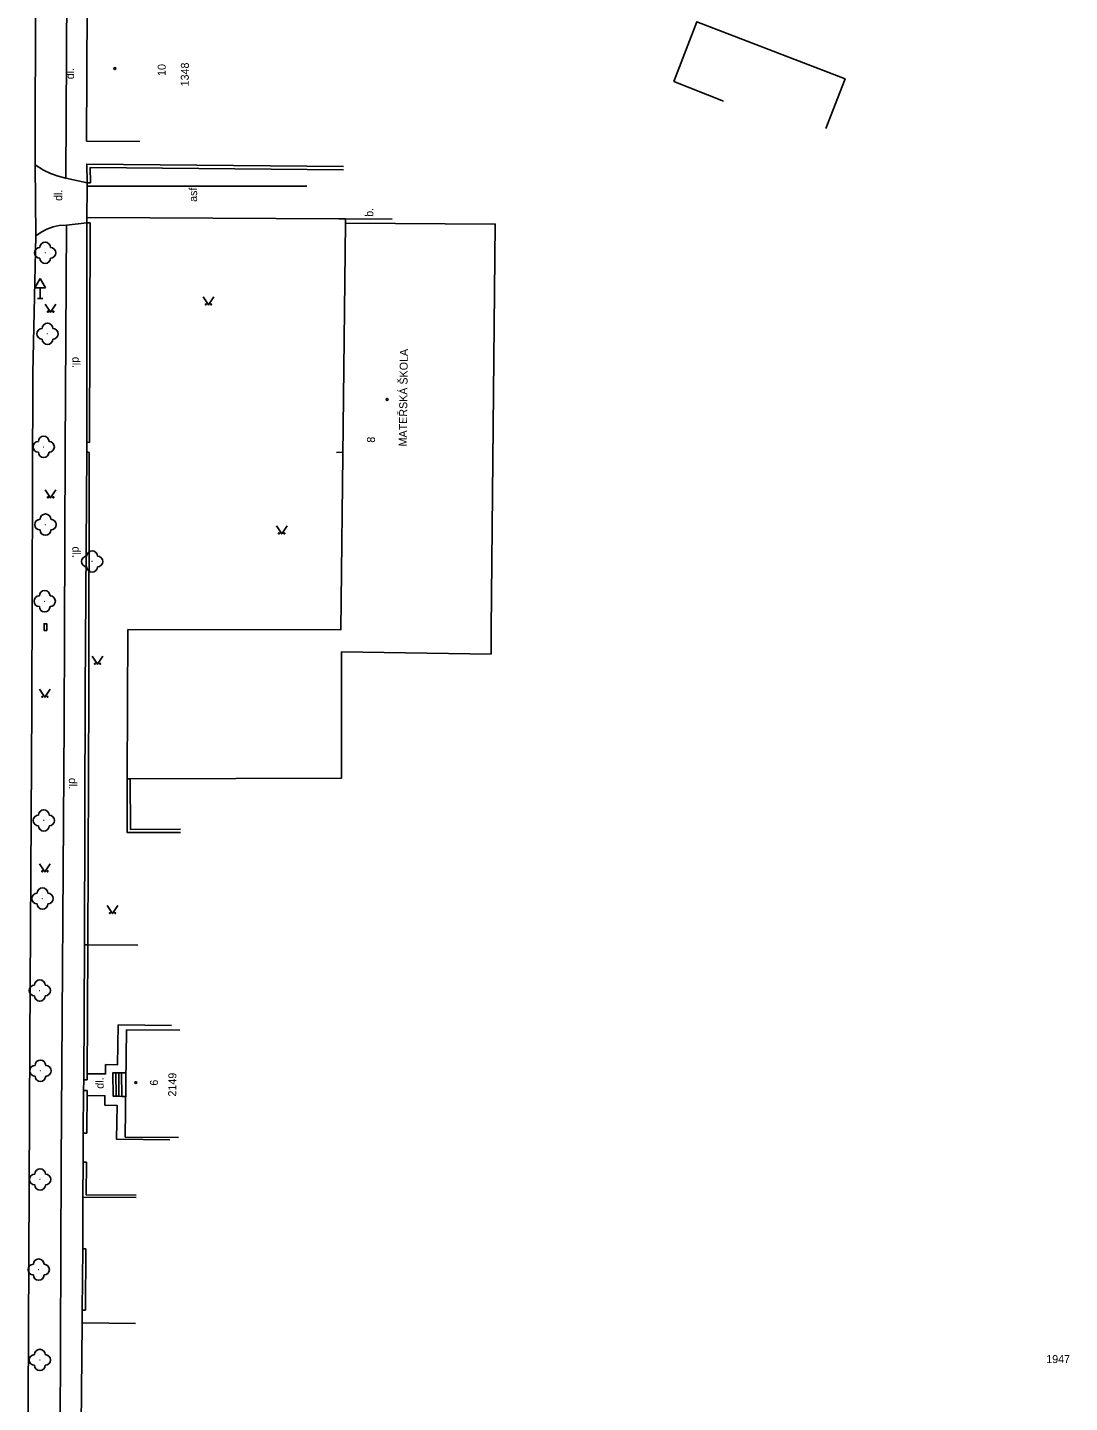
# Model space of a CAD drawing. Extents: x -584400 to -581602, y -1210894 to -1208793.
# Drawn here: x -582839.4 to -582741.8, y -1210331.3 to -1210202.4 of the extents above; entities that cross this region are included whole.
import ezdxf

# ---------------------------------------------------------------- set-up
doc = ezdxf.new("R2010")
doc.units = 0
for name, color, linetype in [('BUDOVY_MĚŘ', 7, 'Continuous'), ('BUDOVY_NEMĚŘ', 7, 'Continuous'), ('OBVOD_PILÍŘE', 7, 'Continuous'), ('POMOC_POPIS', 7, 'Continuous'), ('ROZHRANÍ_PLOCH', 7, 'Continuous'), ('ZELEŇ', 7, 'Continuous'), ('ZN_BUDOV', 7, 'Continuous'), ('ZN_DOPLŇKOVÉ', 7, 'Continuous'), ('ZN_KULTUR', 7, 'Continuous'), ('Č_POPIS_EVID', 7, 'Continuous')]:
    doc.layers.add(name, color=color, linetype=linetype)

msp = doc.modelspace()

# ---------------------------------------------------------------- linework, layer by layer
at = {"layer": 'BUDOVY_MĚŘ'}
for points in [[(-582833.89, -1210213.03), (-582833.81, -1210200.36), (-582829.11, -1210200.42)], [(-582764.59, -1210211.87), (-582762.79, -1210207.21), (-582776.67, -1210201.85), (-582778.85, -1210207.46)], [(-582774.2, -1210209.28), (-582778.85, -1210207.46)], [(-582833.89, -1210213.03), (-582828.89, -1210213.07)], [(-582809.6, -1210220.74), (-582810.06, -1210258.86), (-582830, -1210258.83), (-582830.08, -1210272.82), (-582829.78, -1210272.82)], [(-582830.13, -1210296.33), (-582830.25, -1210306.39), (-582825.25, -1210306.45)], [(-582830.13, -1210296.33), (-582825.13, -1210296.39)], [(-582834.76, -1210371.8), (-582834.29, -1210323.82), (-582829.29, -1210323.87)]]:
    msp.add_lwpolyline(points, dxfattribs=at)
at = {"layer": 'BUDOVY_NEMĚŘ'}
msp.add_lwpolyline([(-582809.6, -1210220.74), (-582795.57, -1210220.82), (-582795.96, -1210258.78), (-582795.96, -1210261.12), (-582809.98, -1210260.9), (-582809.98, -1210272.75), (-582829.78, -1210272.82)], dxfattribs=at)
at = {"layer": 'OBVOD_PILÍŘE'}
msp.add_lwpolyline([(-582837.61, -1210258.59), (-582837.61, -1210258.9), (-582837.86, -1210258.9), (-582837.86, -1210258.28), (-582837.61, -1210258.28), (-582837.61, -1210258.59)], dxfattribs=at)
at = {"layer": 'ROZHRANÍ_PLOCH'}
for points in [[(-582835.81, -1210216.52), (-582835.71, -1210199.03), (-582835.73, -1210172.95)], [(-582838.67, -1210198.71), (-582838.7, -1210215.26)], [(-582835.81, -1210216.52), (-582836.54, -1210216.34), (-582837.25, -1210216.09), (-582837.92, -1210215.76), (-582838.7, -1210215.26)], [(-582838.7, -1210215.26), (-582838.63, -1210221.91)], [(-582835.81, -1210216.52), (-582833.83, -1210216.96)], [(-582833.84, -1210217.26), (-582813.22, -1210217.27)], [(-582838.63, -1210221.91), (-582838.13, -1210221.56), (-582837.59, -1210221.29), (-582837.02, -1210221.09), (-582836.43, -1210220.96), (-582835.76, -1210220.92)], [(-582836.42, -1210350.76), (-582836.25, -1210308.91), (-582835.96, -1210267.6), (-582835.88, -1210241.95), (-582835.76, -1210220.92)], [(-582835.76, -1210220.92), (-582833.86, -1210220.69)], [(-582810.24, -1210220.31), (-582833.85, -1210220.19)], [(-582810.24, -1210220.31), (-582809.6, -1210220.32)], [(-582809.6, -1210220.74), (-582809.6, -1210220.32)], [(-582809.6, -1210220.32), (-582805.24, -1210220.37)], [(-582838.63, -1210221.91), (-582838.91, -1210234.77), (-582838.99, -1210265.95), (-582839.18, -1210297.48), (-582839.41, -1210344.73)], [(-582810.44, -1210242.22), (-582809.86, -1210242.21)], [(-582825.91, -1210295.95), (-582830.91, -1210295.89), (-582830.97, -1210299.61), (-582832.09, -1210299.6), (-582832.1, -1210300.48), (-582833.82, -1210300.47)], [(-582831.13, -1210300.37), (-582831.4, -1210300.36), (-582831.38, -1210302.57), (-582831.11, -1210302.57)], [(-582831.13, -1210300.37), (-582831.11, -1210302.57)], [(-582830.86, -1210300.37), (-582831.13, -1210300.37)], [(-582830.59, -1210300.37), (-582830.86, -1210300.37)], [(-582830.84, -1210302.57), (-582830.86, -1210300.37)], [(-582830.59, -1210300.37), (-582830.57, -1210302.58)], [(-582830.18, -1210300.38), (-582830.59, -1210300.37)], [(-582833.84, -1210302.51), (-582832.15, -1210302.52), (-582832.16, -1210303.42), (-582831.02, -1210303.43), (-582831.06, -1210306.6), (-582826.06, -1210306.66)], [(-582831.11, -1210302.57), (-582830.84, -1210302.57)], [(-582830.84, -1210302.57), (-582830.57, -1210302.58)], [(-582830.57, -1210302.58), (-582830.2, -1210302.58)]]:
    msp.add_lwpolyline(points, dxfattribs=at)
at = {"layer": 'ZELEŇ'}
for centre in [(-582837.75, -1210223.51), (-582837.54, -1210231.1), (-582837.89, -1210241.7), (-582837.73, -1210248.99), (-582833.35, -1210252.44), (-582837.8, -1210256.17), (-582837.88, -1210276.72), (-582838.01, -1210284.04), (-582838.26, -1210292.66), (-582838.2, -1210300.18), (-582838.23, -1210310.37), (-582838.36, -1210318.82), (-582838.25, -1210327.29)]:
    msp.add_circle(centre, 0.0005, dxfattribs=at)
for centre, start, end in [((-582838.25, -1210223.51), 90, 270), ((-582837.75, -1210223.01), 0, 180), ((-582837.25, -1210223.51), 270, 90), ((-582837.75, -1210224.01), 180, 360), ((-582837.54, -1210230.6), 0, 180), ((-582838.04, -1210231.1), 90, 270), ((-582837.04, -1210231.1), 270, 90), ((-582837.54, -1210231.6), 180, 360), ((-582838.39, -1210241.7), 90, 270), ((-582837.89, -1210241.2), 0, 180), ((-582837.39, -1210241.7), 270, 90), ((-582837.89, -1210242.2), 180, 360), ((-582837.73, -1210248.49), 0, 180), ((-582838.23, -1210248.99), 90, 270), ((-582837.23, -1210248.99), 270, 90), ((-582837.73, -1210249.49), 180, 360), ((-582833.85, -1210252.44), 90, 270), ((-582833.35, -1210251.94), 0, 180), ((-582832.85, -1210252.44), 270, 90), ((-582833.35, -1210252.94), 180, 360), ((-582838.3, -1210256.17), 90, 270), ((-582837.8, -1210255.67), 0, 180), ((-582837.3, -1210256.17), 270, 90), ((-582837.8, -1210256.67), 180, 360), ((-582838.38, -1210276.72), 90, 270), ((-582837.88, -1210276.22), 0, 180), ((-582837.38, -1210276.72), 270, 90), ((-582837.88, -1210277.22), 180, 360), ((-582838.51, -1210284.04), 90, 270), ((-582838.01, -1210283.54), 0, 180), ((-582837.51, -1210284.04), 270, 90), ((-582838.01, -1210284.54), 180, 360), ((-582838.26, -1210292.16), 0, 180), ((-582838.76, -1210292.66), 90, 270), ((-582838.26, -1210293.16), 180, 360), ((-582837.76, -1210292.66), 270, 90), ((-582838.7, -1210300.18), 90, 270), ((-582838.2, -1210299.68), 0, 180), ((-582837.7, -1210300.18), 270, 90), ((-582838.2, -1210300.68), 180, 360), ((-582838.73, -1210310.37), 90, 270), ((-582838.23, -1210309.87), 0, 180), ((-582837.73, -1210310.37), 270, 90), ((-582838.23, -1210310.87), 180, 360), ((-582838.86, -1210318.82), 90, 270), ((-582838.36, -1210318.32), 0, 180), ((-582837.86, -1210318.82), 270, 90), ((-582838.36, -1210319.32), 180, 360), ((-582838.75, -1210327.29), 90, 270), ((-582838.25, -1210326.79), 0, 180), ((-582837.75, -1210327.29), 270, 90), ((-582838.25, -1210327.79), 180, 360)]:
    msp.add_arc(centre, 0.5, start, end, dxfattribs=at)
at = {"layer": 'ZN_BUDOV'}
for centre in [(-582831.22, -1210206.24), (-582805.71, -1210237.25), (-582829.26, -1210301.29)]:
    msp.add_circle(centre, 0.0875, dxfattribs=at)
at = {"layer": 'ZN_DOPLŇKOVÉ'}
for p, q in [((-582838.21, -1210225.92), (-582838.71, -1210226.79)), ((-582838.21, -1210225.92), (-582837.71, -1210226.79)), ((-582838.71, -1210226.79), (-582837.71, -1210226.79)), ((-582838.21, -1210227.79), (-582838.21, -1210226.79)), ((-582838.46, -1210227.79), (-582837.96, -1210227.79))]:
    msp.add_line(p, q, dxfattribs=at)
for points in [[(-582833.83, -1210216.96), (-582833.86, -1210215.2), (-582809.8, -1210215.43)], [(-582809.81, -1210215.73), (-582833.53, -1210215.5), (-582833.5, -1210216.96)], [(-582833.83, -1210216.96), (-582833.86, -1210220.69)], [(-582833.83, -1210216.96), (-582833.5, -1210216.96)], [(-582833.6, -1210241.29), (-582833.86, -1210241.27), (-582833.86, -1210220.69), (-582833.53, -1210220.69)], [(-582833.53, -1210220.69), (-582833.6, -1210241.29)], [(-582833.86, -1210241.27), (-582833.86, -1210242.18)], [(-582834.08, -1210288.38), (-582834, -1210264.57), (-582833.86, -1210242.18), (-582833.63, -1210242.24)], [(-582833.63, -1210242.24), (-582833.67, -1210264.57), (-582833.75, -1210288.38)], [(-582825.07, -1210277.84), (-582830.07, -1210277.85), (-582830.08, -1210272.82)], [(-582825.07, -1210277.54), (-582829.77, -1210277.55), (-582829.78, -1210272.82)], [(-582834.14, -1210301.04), (-582834.08, -1210288.38)], [(-582834.08, -1210288.38), (-582833.75, -1210288.38)], [(-582833.75, -1210288.38), (-582833.83, -1210301.04)], [(-582833.75, -1210288.38), (-582829.08, -1210288.41)], [(-582834.19, -1210306.04), (-582834.15, -1210302.04), (-582833.83, -1210302.04)], [(-582834.14, -1210301.04), (-582834.15, -1210302.04)], [(-582834.14, -1210301.04), (-582833.83, -1210301.04)], [(-582833.83, -1210302.04), (-582833.86, -1210306.04)], [(-582834.19, -1210306.04), (-582834.19, -1210308.75)], [(-582834.19, -1210306.04), (-582833.86, -1210306.04)], [(-582829.23, -1210312.05), (-582834.23, -1210312.02), (-582834.19, -1210308.75), (-582833.88, -1210308.75)], [(-582833.88, -1210308.75), (-582833.9, -1210311.82), (-582829.23, -1210311.85)], [(-582834.23, -1210312.02), (-582834.24, -1210316.86)], [(-582834.28, -1210322.62), (-582834.24, -1210316.86), (-582833.94, -1210316.87)], [(-582833.94, -1210316.87), (-582833.98, -1210322.62)], [(-582834.28, -1210322.62), (-582834.29, -1210323.82)], [(-582834.28, -1210322.62), (-582833.98, -1210322.62)]]:
    msp.add_lwpolyline(points, dxfattribs=at)
at = {"layer": 'ZN_KULTUR'}
for points in [[(-582837.74, -1210228.33), (-582837.24, -1210229.08), (-582836.74, -1210228.33)], [(-582822.95, -1210227.65), (-582822.45, -1210228.4), (-582821.95, -1210227.65)], [(-582837.74, -1210245.73), (-582837.24, -1210246.48), (-582836.74, -1210245.73)], [(-582816.09, -1210249.11), (-582815.59, -1210249.86), (-582815.09, -1210249.11)], [(-582833.34, -1210261.33), (-582832.84, -1210262.08), (-582832.34, -1210261.33)], [(-582838.28, -1210264.42), (-582837.78, -1210265.17), (-582837.28, -1210264.42)], [(-582838.28, -1210280.79), (-582837.78, -1210281.54), (-582837.28, -1210280.79)], [(-582831.94, -1210284.7), (-582831.44, -1210285.45), (-582830.94, -1210284.7)]]:
    msp.add_lwpolyline(points, dxfattribs=at)
for centre in [(-582822.7, -1210228.35), (-582822.2, -1210228.35), (-582837.49, -1210229.03), (-582836.99, -1210229.03), (-582837.49, -1210246.43), (-582836.99, -1210246.43), (-582815.84, -1210249.81), (-582815.34, -1210249.81), (-582833.09, -1210262.03), (-582832.59, -1210262.03), (-582838.03, -1210265.12), (-582837.53, -1210265.12), (-582838.03, -1210281.49), (-582837.53, -1210281.49), (-582831.69, -1210285.4), (-582831.19, -1210285.4)]:
    msp.add_circle(centre, 0.05, dxfattribs=at)

# ---------------------------------------------------------------- texts
at = {"layer": 'POMOC_POPIS'}
for s, rotation, p in [('dl.', 89.6626, (-582835.06, -1210207.24)), ('asf.', 89.6673, (-582823.52, -1210218.74)), ('dl.', 89.6673, (-582836.16, -1210218.65)), ('b.', 89.6673, (-582807.01, -1210220.14)), ('MATEŘSKÁ ŠKOLA', 89.3087, (-582803.87, -1210241.66)), ('dl.', 269.6731, (-582835.2, -1210233.26)), ('dl.', 269.8213, (-582835.2, -1210251.04)), ('dl.', 269.5978, (-582835.53, -1210272.73)), ('dl.', 89.3166, (-582832.28, -1210301.87))]:
    msp.add_text(s, height=0.75, rotation=rotation, dxfattribs=at).set_placement(p)
at = {"layer": 'Č_POPIS_EVID'}
for s, rotation, p in [('10', 89.8575, (-582826.46, -1210206.93)), ('1348', 89.6382, (-582824.3, -1210207.91)), ('8', 89.3087, (-582806.85, -1210241.31)), ('2149', 89.3521, (-582825.48, -1210302.6)), ('6', 89.3166, (-582827.19, -1210301.58))]:
    msp.add_text(s, height=0.75, rotation=rotation, dxfattribs=at).set_placement(p)
msp.add_text('1947', height=0.75, dxfattribs=at).set_placement((-582743.94, -1210327.58))

doc.saveas('drawing.dxf')
